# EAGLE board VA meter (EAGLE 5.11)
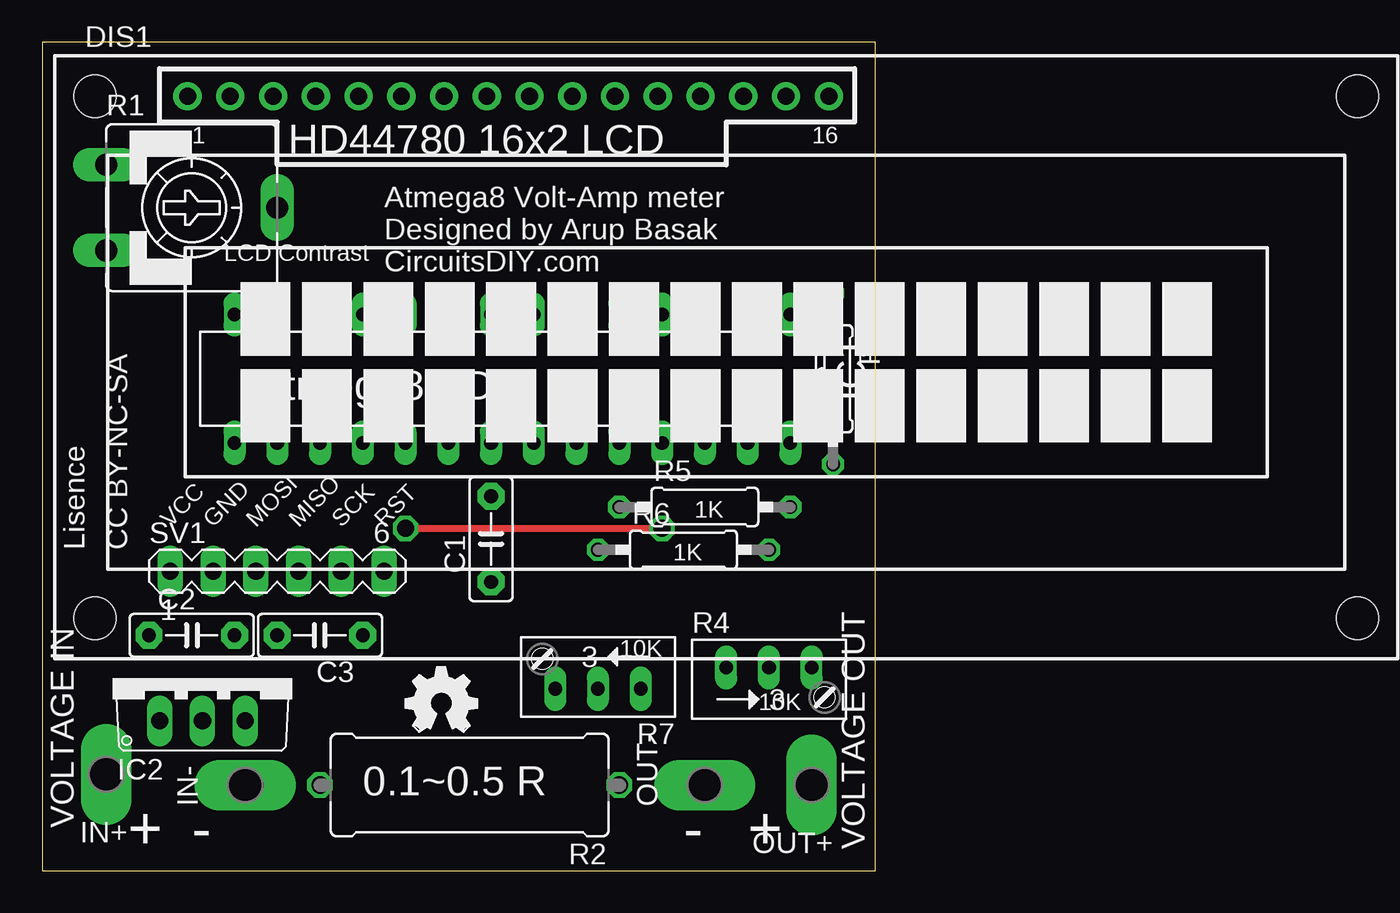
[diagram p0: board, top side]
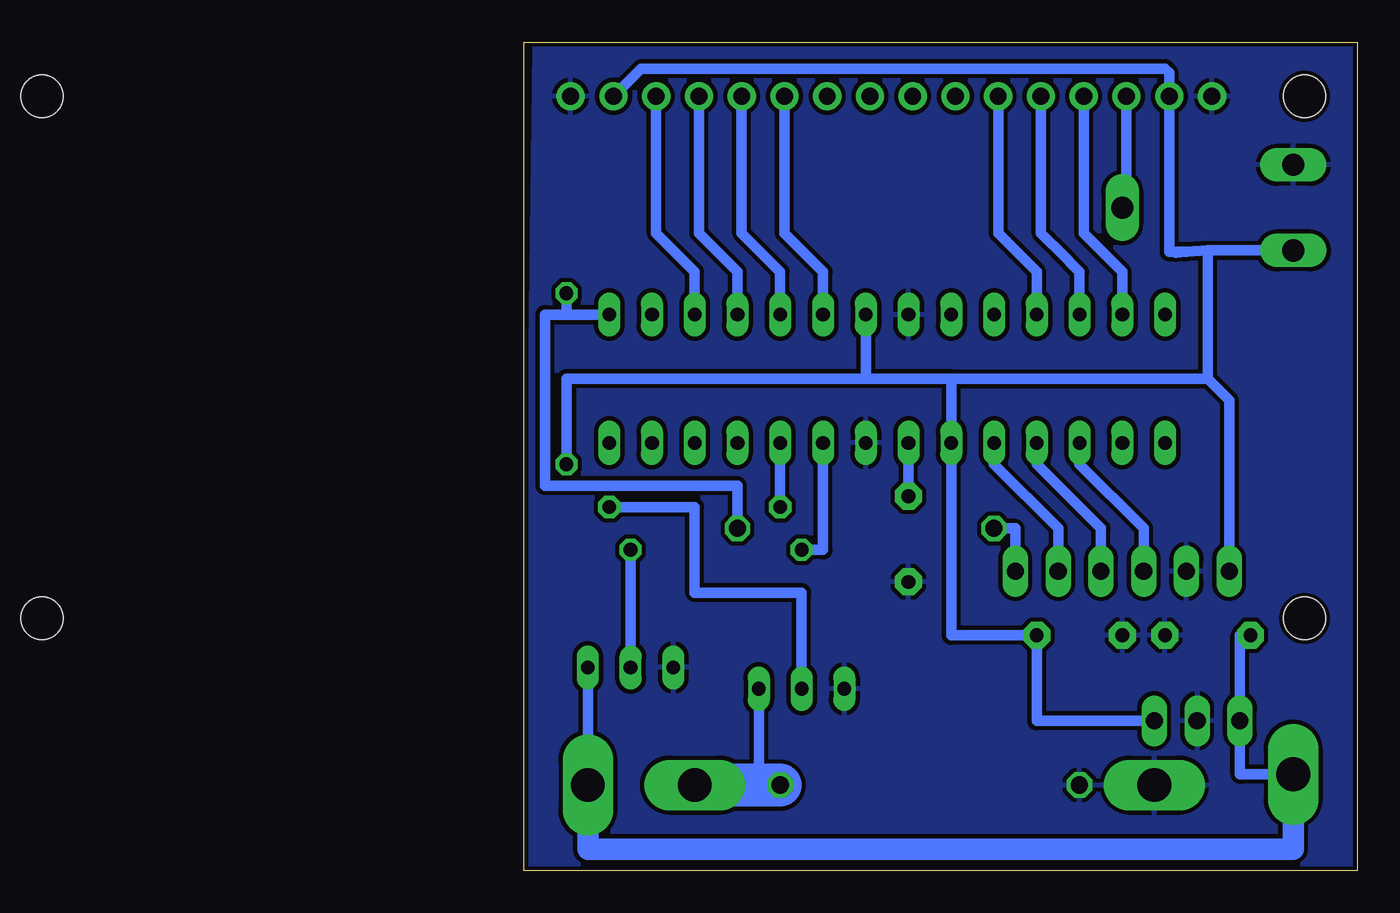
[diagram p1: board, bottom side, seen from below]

Size 49.51 x 49.2 mm. Coordinates in mm from the lower left corner, seen from the top.
Outline: 0,0 49.51,0 49.51,49.2 0,49.2 0,0
Copper layers (1*16): Top 0.035mm / dielectric 1.5mm / Bottom 0.035mm
Design rules "Fusion_eagle_rule_v1.1": minimum track width 6mil, minimum drill 12mil, track to track 6mil, track to pad 6mil, pad to pad 6mil, via to via 6mil, smd to smd 0mil, copper to edge 10mil, drill to drill 10mil, minimum pad ring 10mil, minimum via ring 6mil, stop-mask expansion 2mil, vias tented up to drill 100mil, thermal gap 10mil

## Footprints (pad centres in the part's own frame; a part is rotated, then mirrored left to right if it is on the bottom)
C5B2.5 = drill 0.813 pad 1.6 octagon: 1 -2.54,0; 2 2.54,0
TUXGR_16X2_R2 = drill 1 pad 1.676 round: 1 -32,15.5; 2 -29.46,15.5; 3 -26.92,15.5; 4 -24.38,15.5; 5 -21.84,15.5; 6 -19.3,15.5; 7 -16.76,15.5; 8 -14.22,15.5; 9 -11.68,15.5; 10 -9.14,15.5; 11 -6.6,15.5; 12 -4.06,15.5; 13 -1.52,15.5; 14 1.02,15.5; 15 3.56,15.5; 16 6.1,15.5 | hole 2.5: -37.5,-15.5; 37.5,-15.5; -37.5,15.5; 37.5,15.5
DIL28-3 = drill 0.813 long: 1 -16.51,-3.81; 2 -13.97,-3.81; 3 -11.43,-3.81; 4 -8.89,-3.81; 5 -6.35,-3.81; 6 -3.81,-3.81; 7 -1.27,-3.81; 8 1.27,-3.81; 9 3.81,-3.81; 10 6.35,-3.81; 11 8.89,-3.81; 12 11.43,-3.81; 13 13.97,-3.81; 14 16.51,-3.81; 15 16.51,3.81; 16 13.97,3.81; 17 11.43,3.81; 18 8.89,3.81; 19 6.35,3.81; 20 3.81,3.81; 21 1.27,3.81; 22 -1.27,3.81; 23 -3.81,3.81; 24 -6.35,3.81; 25 -8.89,3.81; 26 -11.43,3.81; 27 -13.97,3.81; 28 -16.51,3.81
TO220V = drill 1.016 long: 1 -2.54,-2.54; 2 0,-2.54; 3 2.54,-2.54
P1-20Y = drill 2.007 pad 2.54 long: 1 0,0
CA9V = drill 1.321 long: A -2.54,-5.08; E 2.54,-5.08; S 0,5.08
0617/17 = drill 1.016 octagon: 1 -8.89,0; 2 8.89,0
0207/10 = drill 0.813 octagon: 1 -5.08,0; 2 5.08,0
RJ9W = drill 0.813 long: A 2.54,0.635; E -2.54,0.635; S 0,0.635
MA06-1 = drill 1.016 long: 1 -6.35,0; 2 -3.81,0; 3 -1.27,0; 4 1.27,0; 5 3.81,0; 6 6.35,0

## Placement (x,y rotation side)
C1  100kpf  [C5B2.5]  26.67,19.68 90 top
C2  22uF  [C5B2.5]  8.89,13.97 0 top
C3  22uF  [C5B2.5]  16.51,13.97 180 top
DIS1  TUXGR_16X2_R2  [TUXGR_16X2_R2]  40.64,30.48 0 top
IC1  MEGA8-P  [DIL28-3]  27.94,29.21 180 top
IC2  7805TV  [TO220V]  9.53,11.43 0 top
IN+  TPPAD1-20Y  [P1-20Y]  3.81,5.71 180 top
IN-  TPPAD1-20Y  [P1-20Y]  12.06,5.08 90 top
OUT+  TPPAD1-20Y  [P1-20Y]  45.72,5.08 180 top
OUT-  TPPAD1-20Y  [P1-20Y]  39.37,5.08 90 top
R1  10K  [CA9V]  8.89,39.37 270 top
R2  0.25E  [0617/17]  25.4,5.08 180 top
R3  10K  [0207/10]  46.99,29.21 270 top
R4  10k  [RJ9W]  43.18,11.43 0 top
R5  1K  [0207/10]  39.37,21.59 0 top
R6  1K  [0207/10]  38.1,19.05 0 top
R7  10k  [RJ9W]  33.02,11.43 180 top
SV1  ISP  [MA06-1]  13.97,17.78 0 top
U$1  [OSHW_FILLX150_NOTEXT]  21.59,8.26 0 top

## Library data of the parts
C1-C3 = capacitor-wima
DIS1 = display-lcd
IC1 = atmel
IC2 = linear
IN+ IN- OUT+ OUT- = testpad
R1 R4 R7 = pot
R2 R3 R5 R6 = rcl
SV1 = con-lstb; OC_FARNELL: unknown; OC_NEWARK: unknown
U$1 = ohw-logo

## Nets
$222: OUT-.1 R2.1 R7.E
+VE: C2.1 IC2.1 IN+.1 OUT+.1 R4.A
AMP_SENSE: R5.2 R7.S
GND: C1.1 C2.2 C3.2 DIS1.1 DIS1.16 IC1.8 IC1.22 IC2.2 IN-.1 R1.A R2.2 R4.E R7.A SV1.2
MISO: IC1.18 SV1.4
MOSI: IC1.17 SV1.3
N$1: DIS1.3 R1.S
N$2: DIS1.4 IC1.13
N$3: DIS1.5 IC1.12
N$4: DIS1.6 IC1.11
N$5: DIS1.11 IC1.6
N$6: DIS1.12 IC1.5
N$7: DIS1.13 IC1.4
N$8: DIS1.14 IC1.3
N$9: C1.2 IC1.21
N$13: IC1.24 R5.1
N$14: IC1.23 R6.1
RST: IC1.1 R3.1 SV1.6
SCK: IC1.19 SV1.5
VCC: C3.1 DIS1.2 DIS1.15 IC1.7 IC1.20 IC2.3 R1.E R3.2 SV1.1
VOLT_SENSE: R4.S R6.2

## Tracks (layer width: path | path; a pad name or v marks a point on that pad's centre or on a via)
$222
  Bottom 0.61: 35.56,5.08 R7.E
  Bottom 2.54: R2.1 35.56,5.08 OUT-.1
+VE
  Bottom 0.61: IN+.1 6.99,5.71 IC2.1 6.99,13.97 C2.1 | OUT+.1 R4.A
  Bottom 1.27: IN+.1 3.81,1.27 45.72,1.27 OUT+.1
AMP_SENSE
  Bottom 0.61: R5.2 39.37,21.59 39.37,16.51 33.02,16.51 R7.S
GND
  pour Bottom (isolate 0.254): 0,48.9 48.9,48.9 49.53,0 0,0
MISO
  Bottom 0.61: IC1.18 19.05,24.13 15.24,20.32 SV1.4
MOSI
  Bottom 0.61: IC1.17 16.51,24.13 12.7,20.32 SV1.3
N$1
  Bottom 0.61: DIS1.3 13.72,40.39 R1.S
N$2
  Bottom 0.61: IC1.13 13.97,35.56 16.26,37.85 DIS1.4
N$3
  Bottom 0.61: IC1.12 16.51,35.56 17.78,36.83 18.41,37.47 18.8,37.85 DIS1.5
N$4
  Bottom 0.61: IC1.11 19.05,35.56 20.32,36.83 20.95,37.47 21.34,37.85 DIS1.6
N$5
  Bottom 0.61: IC1.6 31.75,35.56 34.04,37.85 DIS1.11
N$6
  Bottom 0.61: IC1.5 34.29,35.56 36.58,37.85 DIS1.12
N$7
  Bottom 0.61: IC1.4 36.83,35.56 39.12,37.85 DIS1.13
N$8
  Bottom 0.61: IC1.3 39.37,35.56 41.66,37.85 DIS1.14
N$9
  Bottom 0.61: C1.2 IC1.21
N$13
  Bottom 0.61: R5.1 IC1.24
N$14
  Bottom 0.61: IC1.23 31.75,19.05 R6.1
RST  (via drill 1)
  Top 0.406: v21.59,20.32 v36.83,20.32
  Bottom 0.61: R3.1 46.99,33.02 IC1.1 48.26,33.02 48.26,22.86 36.83,22.86 v36.83,20.32 | SV1.6 20.32,19.05 20.32,20.32 v21.59,20.32
SCK
  Bottom 0.61: IC1.19 21.59,24.13 17.78,20.32 SV1.5
VCC
  Bottom 0.61: 8.89,36.83 R1.E | 8.89,36.83 10.15,36.75 | 10.15,36.75 10.79,36.7 | DIS1.15 42.55,47.62 11.43,47.62 11.18,47.38 DIS1.2 11.18,36.75 10.15,36.75 | 24.13,29.21 IC1.20 24.13,13.97 C3.1 19.05,8.89 IC2.3 | 24.13,29.21 29.21,29.21 | 29.21,29.21 IC1.7 | R3.2 46.99,29.21 29.21,29.21 | 24.13,29.21 8.89,29.21 | 8.89,29.21 8.89,36.83 | SV1.1 7.62,27.94 8.89,29.21
VOLT_SENSE
  Bottom 0.61: R4.S R6.2

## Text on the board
tNames: 1 | HD44780 16x2 LCD | 16 | Atmega8 Volt-Amp meter | Designed by Arup Basak | LCD Contrast | CircuitsDIY.com | Atmega8 PDIP | 1K | VCC | GND | MOSI | MISO | SCK | RST | Lisence | CC BY-NC-SA | 1K | 10K | 10K | 0.1~0.5 R | VOLTAGE IN | + | - | - | + | VOLTAGE OUT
